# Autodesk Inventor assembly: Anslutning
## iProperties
Company: Autodesk EMEA
Shininess: 64.0
Length Units: 11269
Angle Units: 11279
Time Units: 11290
Mass Units: 11283
Length Display Precision: 3
Angle Display Precision: 2
Compacted: True
Created: 2002-08
Part Number: Anslutning
Document SubType Name: Assembly
Designer: Franz Kaltseis
Density: 0.0
Volumn: 0.0
Area: 0.0
PropertySet Name: Model Information
Control State: 0
Master: False
Checked Out: False
Author: Franz Kaltseis
